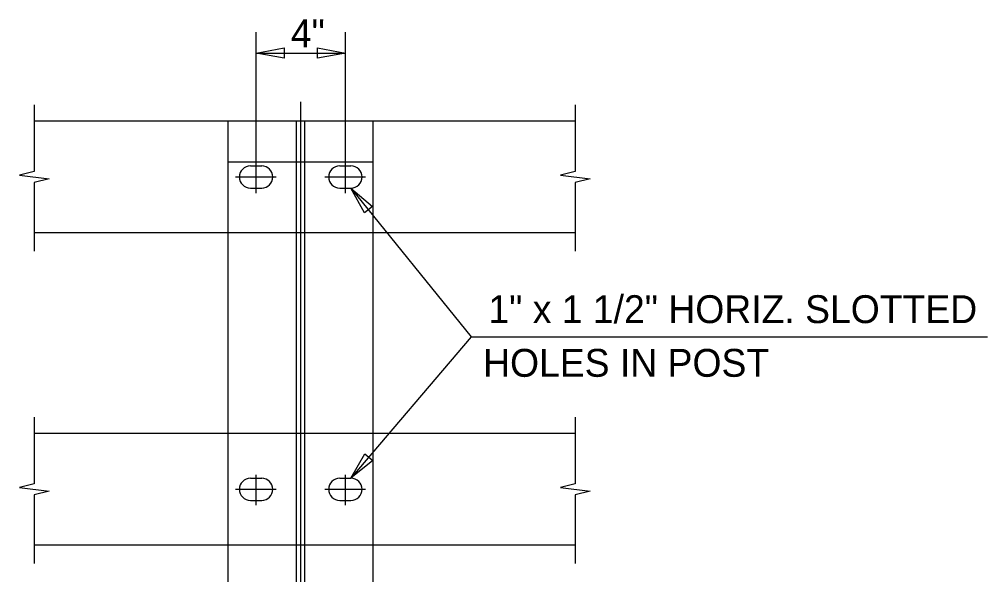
# Model space of a CAD drawing. Extents: x 0 to 45.3, y 0 to 31.4.
# Drawn here: x 23.63 to 30.87, y 10.52 to 14.66 of the extents above; entities that cross this region are included whole.
import ezdxf

# ---------------------------------------------------------------- set-up
doc = ezdxf.new("R2010")
doc.units = 0
for name, color, linetype in [('BRDG_ANNO_General-Notes', 7, 'Continuous'), ('BRDG_BASE_Active-Point', 7, 'Continuous'), ('BRDG_BASE_Dtlctrln', 7, 'Continuous'), ('BRDG_BASE_Hidden-Line', 7, 'Continuous'), ('BRDG_BASE_Obj-Line', 7, 'Continuous'), ('Default', 7, 'Continuous')]:
    doc.layers.add(name, color=color, linetype=linetype)

# ---------------------------------------------------------------- blocks, each defined once
blk = doc.blocks.new('TERM')
at = {"layer": 'Default'}
for p, q in [((-1.6, -0.267), (-1.6, 0.267)), ((-1.6, 0.267), (0, 0)), ((0, 0), (-1.6, -0.267))]:
    blk.add_line(p, q, dxfattribs=at)

msp = doc.modelspace()

# ---------------------------------------------------------------- linework, layer by layer
at = {"layer": 'BRDG_ANNO_General-Notes'}
for p, q in [((25.4025, 14.4133), (26.0691, 14.4133)), ((26.1108, 13.4038), (27.0081, 12.2927)), ((26.2105, 13.2186), (26.1108, 13.4038)), ((26.1108, 13.4038), (26.2708, 13.2674)), ((26.2708, 13.2674), (26.2105, 13.2186)), ((27.0081, 12.2927), (26.1108, 11.2371)), ((27.0081, 12.2927), (30.8654, 12.2927)), ((26.1108, 11.2371), (26.2151, 11.4197)), ((26.2742, 11.3695), (26.1108, 11.2371)), ((26.2151, 11.4197), (26.2742, 11.3695))]:
    msp.add_line(p, q, dxfattribs=at)
at = {"layer": 'BRDG_BASE_Active-Point'}
for p, q in [((25.4025, 13.4871), (25.4025, 13.4871)), ((26.0691, 13.4871), (26.0691, 13.4871)), ((25.4025, 11.1538), (25.4025, 11.1538)), ((26.0691, 11.1538), (26.0691, 11.1538))]:
    msp.add_line(p, q, dxfattribs=at)
at = {"layer": 'BRDG_BASE_Dtlctrln'}
for p, q in [((25.4025, 13.3675), (25.4025, 14.5696)), ((26.0691, 13.3675), (26.0691, 14.5696)), ((25.7358, 8.0704), (25.7358, 14.049)), ((25.2487, 13.4871), (25.5526, 13.4871)), ((25.9154, 13.4871), (26.2193, 13.4871)), ((25.4025, 11.0342), (25.4025, 11.2625)), ((26.0691, 11.0342), (26.0691, 11.2625)), ((25.2487, 11.1538), (25.5526, 11.1538)), ((25.9154, 11.1538), (26.2193, 11.1538))]:
    msp.add_line(p, q, dxfattribs=at)
at = {"layer": 'BRDG_BASE_Hidden-Line'}
for p, q in [((25.1941, 10.0704), (25.1941, 13.9038)), ((25.7045, 10.0704), (25.7045, 13.9038)), ((25.767, 10.0704), (25.767, 13.9038)), ((26.2775, 10.0704), (26.2775, 13.9038)), ((26.2775, 13.5982), (25.1941, 13.5982)), ((25.3608, 13.5705), (25.4441, 13.5705)), ((26.0275, 13.5705), (26.1108, 13.5705)), ((25.3608, 13.4038), (25.4441, 13.4038)), ((26.0275, 13.4038), (26.1108, 13.4038)), ((25.3608, 11.2371), (25.4441, 11.2371)), ((26.0275, 11.2371), (26.1108, 11.2371)), ((25.3608, 11.0705), (25.4441, 11.0705)), ((26.0275, 11.0705), (26.1108, 11.0705))]:
    msp.add_line(p, q, dxfattribs=at)
for centre, start, end in [((25.3608, 13.4871), 90, 180), ((25.4441, 13.4871), 0, 90), ((26.0275, 13.4871), 90, 180), ((26.1108, 13.4871), 0, 90), ((25.3608, 13.4871), 180, 270), ((25.4441, 13.4871), 270, 360), ((26.0275, 13.4871), 180, 270), ((26.1108, 13.4871), 270, 360), ((25.3608, 11.1538), 90, 180), ((25.4441, 11.1538), 0, 90), ((26.0275, 11.1538), 90, 180), ((26.1108, 11.1538), 0, 90), ((25.3608, 11.1538), 180, 270), ((25.4441, 11.1538), 270, 360), ((26.0275, 11.1538), 180, 270), ((26.1108, 11.1538), 270, 360)]:
    msp.add_arc(centre, 0.0833, start, end, dxfattribs=at)
at = {"layer": 'BRDG_BASE_Obj-Line'}
for p, q in [((27.7856, 13.9038), (23.7453, 13.9038)), ((27.7856, 13.0704), (23.7453, 13.0704)), ((25.1941, 11.5705), (25.1941, 13.0704)), ((26.2775, 11.5705), (26.2775, 13.0704)), ((27.7856, 11.5705), (23.7453, 11.5705)), ((27.7856, 10.737), (23.7453, 10.737)), ((25.1941, 10.0704), (25.1941, 10.737)), ((26.2775, 10.0704), (26.2775, 10.737))]:
    msp.add_line(p, q, dxfattribs=at)
for points in [[(23.7453, 14.0258), (23.7453, 13.5288), (23.6342, 13.501), (23.8564, 13.4732), (23.7453, 13.4455), (23.7453, 12.9322)], [(27.7856, 14.0258), (27.7856, 13.5288), (27.6745, 13.501), (27.8967, 13.4732), (27.7856, 13.4455), (27.7856, 12.9322)], [(23.7453, 11.6925), (23.7453, 11.1955), (23.6342, 11.1677), (23.8564, 11.1399), (23.7453, 11.1121), (23.7453, 10.5988)], [(27.7856, 11.6925), (27.7856, 11.1955), (27.6745, 11.1677), (27.8967, 11.1399), (27.7856, 11.1121), (27.7856, 10.5988)]]:
    msp.add_lwpolyline(points, dxfattribs=at)

# ---------------------------------------------------------------- block references
at = {"layer": 'BRDG_ANNO_General-Notes', "xscale": 0.13020833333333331, "yscale": 0.146484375, "rotation": 180}
msp.add_blockref('TERM', (25.4025, 14.4133), dxfattribs=at)
at = {"layer": 'BRDG_ANNO_General-Notes', "xscale": 0.13020833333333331, "yscale": 0.146484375}
msp.add_blockref('TERM', (26.0691, 14.4133), dxfattribs=at)

# ---------------------------------------------------------------- texts
at = {"layer": 'BRDG_ANNO_General-Notes'}
for s, height, p in [('4"', 0.20833, (25.6615, 14.4566)), ('1" x 1 1/2" HORIZ. SLOTTED', 0.208333, (27.1371, 12.3954)), ('HOLES IN POST', 0.208333, (27.0974, 11.9943))]:
    msp.add_text(s, height=height, dxfattribs=at).set_placement(p)

doc.saveas('drawing.dxf')
